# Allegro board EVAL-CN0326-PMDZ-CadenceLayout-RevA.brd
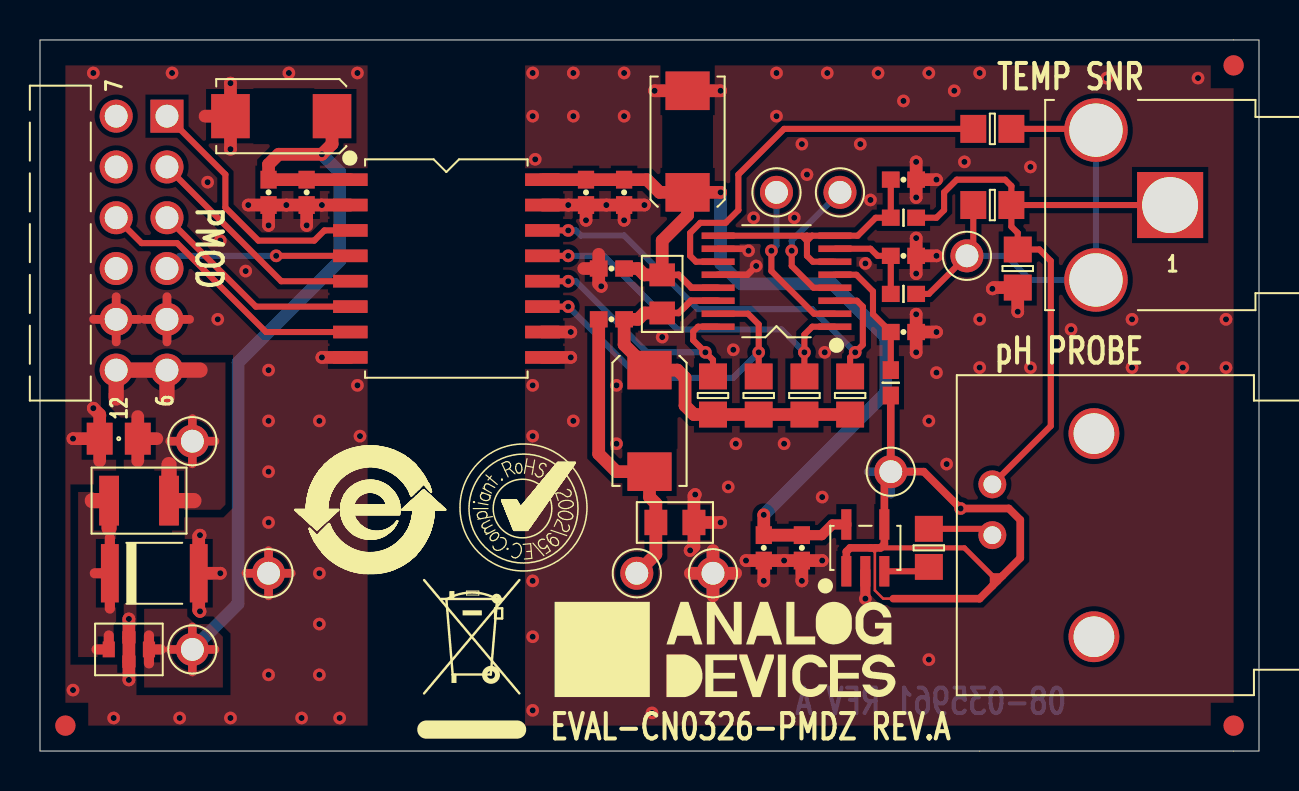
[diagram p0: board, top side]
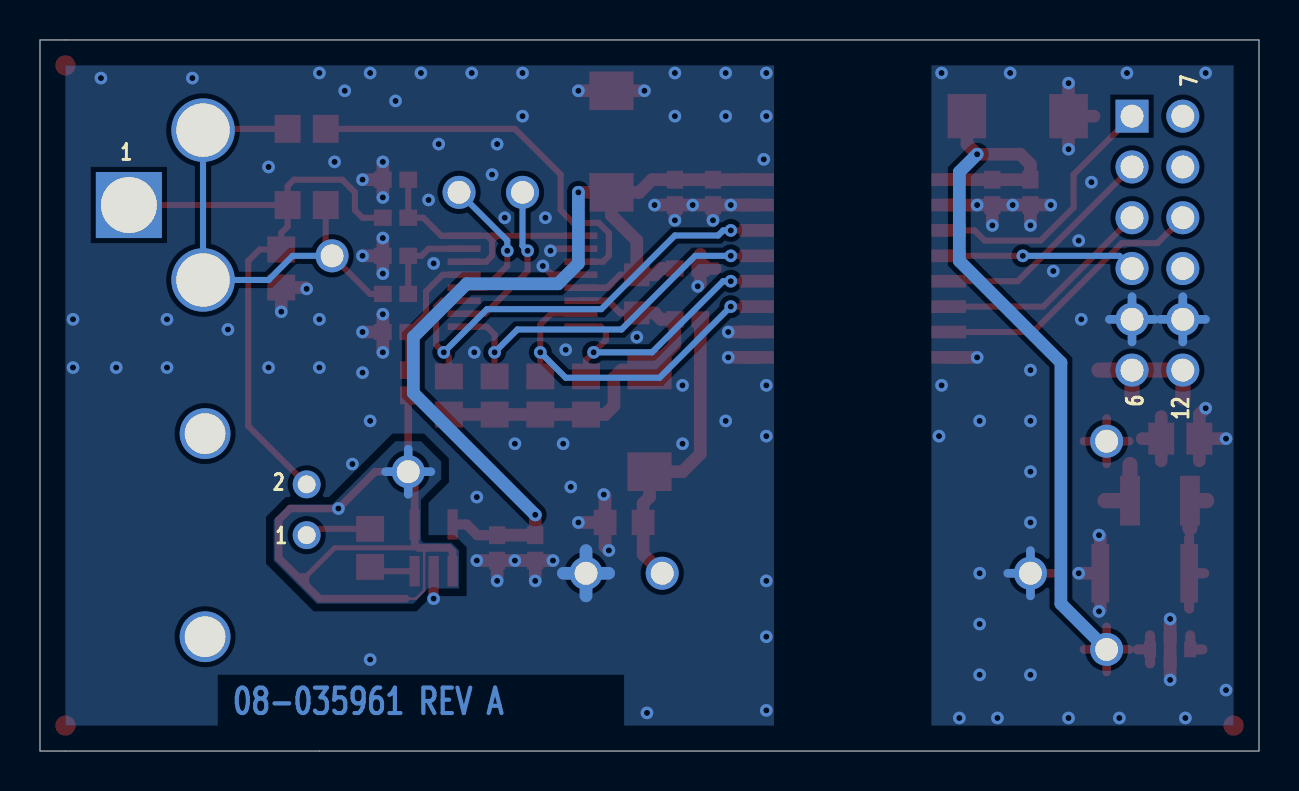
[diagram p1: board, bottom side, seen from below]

Outline 60.96 x 35.56 mm; copper layers: TOP, BOTTOM. Coordinates in mm from the lower left corner of the outline.
Outline path: 0,35.56 0,0 60.96,0 60.96,35.56 0,35.56

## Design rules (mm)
nets with their own width: min track width 0.508; nets AGND

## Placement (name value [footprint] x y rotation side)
C1  4.7UF  [C0805]  3.94 15.62 180 top
C2  100nF  [C0402]  36.2 10.16 90 top
C4  100nF  [C0402]  29.21 27.94 90 top
C5  10000pF  [C0402]  27.3 27.94 90 top
C6  10uF  [C2312]  12.06 31.75 180 top
C7  100nF  [C0402]  11.43 27.94 90 top
C8  10000pF  [C0402]  13.34 27.94 90 top
C9  10000pF  [C0402]  38.1 10.16 90 top
C10  1uF  [C0402]  43.18 20.95 180 top
C11  1uF  [C0402]  43.18 24.77 180 top
C12  1uF  [C0402]  43.18 28.57 180 top
C13  10uF  [C2312]  32.38 30.48 90 top
C14  100nF  [C0402]  28.58 24.13 0 top
C15  10uF  [C2312]  30.48 16.51 270 top
C16  100nF  [C0402]  28.58 21.59 0 top
CR1  DL4729A-TP  [DL41-2]  5.71 8.89 0 top
E1  330OHM  [L0805]  31.75 11.43 180 top
E2  330OHM  [L0805]  31.12 22.86 270 top
F1  0.35A  [F1210]  4.95 12.52 180 top
FR1  1uF  [C0805-4P]  4.44 5.08 0 top
J1  1-1634622-0  [CNAMP227161-1]  47.62 10.79 0 top
J2  TSW-106-25-F-D-RA  [CNHDRRA2X6H240]  6.35 31.75 270 top
NOREF  -  []  21.59 5.71 0 top
NOREF#2  -  [unnamed#2]  59.69 34.29 0 top
NOREF#3  -  []  -19.69 -47.12 0 top
NOREF#4  -  []  0 35.56 0 top
NOREF#5  -  []  60.96 0 90 top
NOREF#6  -  []  20.83 73.91 0 top
NOREF#7  -  []  0 0 0 top
NOREF#8  -  []  1.27 1.27 0 top
NOREF#9  -  []  0 0 0 top
NOREF#10  -  []  -136.53 -239.08 0 top
NOREF#11  -  [unnamed#2]  1.27 1.27 0 top
NOREF#12  -  []  60.96 0 90 top
NOREF#13  -  []  -136.53 -239.08 0 top
NOREF#14  -  []  0 0 0 top
NOREF#15  -  []  60.96 0 0 top
NOREF#16  -  []  60.96 35.56 180 top
NOREF#17  -  []  1.27 1.27 0 top
NOREF#18  -  []  16.51 12.06 0 top
NOREF#19  -  []  -136.53 -239.08 0 top
NOREF#20  -  []  24.13 12.06 0 top
NOREF#21  -  []  0 35.56 270 top
NOREF#22  -  []  34.29 5.08 0 top
NOREF#23  -  []  0 35.56 0 top
NOREF#24  -  [unnamed#2]  59.69 1.27 0 top
NOREF#25  -  []  -34.61 140.02 0 top
P1  PJRAN1X1U03X  [CNTHRAL768W394H522]  56.52 27.3 180 top
R1  5K  [R0805]  47.62 27.3 180 top
R2  5K  [R0805]  48.9 24.13 90 top
R3  0  [R0805]  47.62 31.11 0 top
R4  10K  [R0402]  42.55 18.41 90 top
R5  10K  [R0402]  43.18 22.86 180 top
R6  10K  [R0402]  43.18 26.67 180 top
R7  100K  [R0805]  40.51 17.78 270 top
R8  100K  [R0805]  38.23 17.78 270 top
R9  100K  [R0805]  33.66 17.78 90 top
R10  1MEG  [R0805]  44.45 10.16 270 top
R11  100K  [R0805]  35.94 17.78 90 top
TP1  TESTPAD  [TPC65D45]  7.62 15.49 180 top
TP2  TESTPAD  [TPC65D45]  42.55 13.97 0 top
TP3  TESTPAD  [TPC65D45]  46.36 24.77 0 top
TP4  TESTPAD  [TPC65D45]  7.62 5.08 180 top
TP5  TESTPAD  [TPC65D45]  33.66 8.89 0 top
TP6  TESTPAD  [TPC65D45]  29.84 8.89 0 top
TP7  TESTPAD  [TPC65D45]  36.83 27.94 180 top
TP8  TESTPAD  [TPC65D45]  40.01 27.94 180 top
TP19  TESTPAD  [TPC65D45]  11.43 8.89 0 top
U1  AD8603AUJZ  [TSOT-5]  41.27 10.16 0 top
U2  AD7793BRUZ  [TSSOP16]  36.83 23.5 90 top
U4  ADUM5401ARWZ  [SO16WB]  20.32 24.13 270 top

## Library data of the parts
C1 = CAP: Tolerance: 10; User Part Number: UPN; alternate symbols: (C0402H22_ALT,C0201-2,C0402_A); part number: CAP_SM-4.7UF,25V,10,E006908,C0805; tolerance: 10
C2 C4 C7 C14 C16 = CAP: Tolerance: 15; User Part Number: UPN; alternate symbols: (C0402H22_ALT,C0201-2,C0402_A); part number: CAP_SM-100NF,10V,15,E007265,C0402; tolerance: 15
C5 C8 C9 = CAP: Tolerance: 10; User Part Number: UPN; alternate symbols: (C0402H22_ALT,C0201-2,C0402_A); part number: CAP_SM-10000PF,25V,10,E013688,C0402; tolerance: 10
C6 C13 C15 = CAPP: Tolerance: 20; User Part Number: UPN; part number: CAPP_SM-10UF,35V,20,E013369,C2312; tolerance: 20
C10-C12 = CAP: Tolerance: 10; User Part Number: UPN; alternate symbols: (C0402H22_ALT,C0201-2,C0402_A); part number: CAP_SM-1UF,10V,10,E011429,C0402; tolerance: 10
CR1 = DIOZNR: Tolerance: 5; User Part Number: UPN; part number: DIOZNR_SM-DL4729A-TP,3.6V,5,E013494,DL41-2; tolerance: 5
E1 E2 = FERRITE: Tolerance: 25; User Part Number: UPN; part number: FERRITE_SM-330OHM,25,E018120,L0805; tolerance: 25
F1 = FSFUSE: User Part Number: UPN; part number: FSFUSE_SM-0.35A,6V,E016918,F1210
FR1 = CAP4P_V3: Tolerance: 20; User Part Number: UPN; part number: CAP4P_V3_SM-1UF,16V,20,E014204,C0805-4P; tolerance: 20
J1 = CNBNC2P: User Part Number: UPN; part number: CNBNC2P_TH-1-1634622-0,E008038,CNAMP227161-1
J2 = CN12P_V3: User Part Number: UPN; part number: CN12P_V3_TH-TSW-106-25-F-D-RA,E018495,CNHDRRA2X6H240
P1 = CN3P_V3: User Part Number: UPN; part number: CN3P_V3_TH-PJRAN1X1U03X,E013427,CNTHRAL768W394H522
R1 R2 = RES: Tolerance: 0.1; User Part Number: UPN; alternate symbols: (RRAD984L1500W75H520LD32;TO220H590_ALT;R0402_A); part number: RES_SM-5K,1/5W,0.1,E014315,R0805; tolerance: 0.1
R3 = RES: Tolerance: 1; User Part Number: UPN; alternate symbols: (RRAD984L1500W75H520LD32;TO220H590_ALT;R0402_A); part number: RES_SM-0,1/10W,1,E004152,R0805; tolerance: 1
R4-R6 = RES: Tolerance: 0.1; User Part Number: UPN; alternate symbols: (RRAD984L1500W75H520LD32;TO220H590_ALT;R0402_A); part number: RES_SM-10K,1/16W,0.1,E012474,R0402; tolerance: 0.1
R7-R9 R11 = RES: Tolerance: 0.1; User Part Number: UPN; alternate symbols: (RRAD984L1500W75H520LD32;TO220H590_ALT;R0402_A); part number: RES_SM-100K,1/10W,0.1,E003805,R0805; tolerance: 0.1
R10 = RES: Tolerance: 1; User Part Number: UPN; alternate symbols: (RRAD984L1500W75H520LD32;TO220H590_ALT;R0402_A); part number: RES_SM-1MEG,1/8W,1,E018283,R0805; tolerance: 1
TP1-TP8 TP19 = NCTESTPAD: User Part Number: UPN; part number: NCTESTPAD_TH-TESTPAD,E013404,TPC65D45
U1 = AD8603: User Part Number: UPN; part number: AD8603_SM-AD8603AUJZ,E007335,TSOT-5,AD8603
U2 = AD779X_V4: User Part Number: UPN; part number: AD779X_V4_SM-AD7793BRUZ,E018367,TSSOP16,N/A
U4 = ADUM5401: User Part Number: UPN; part number: ADUM5401_SM-ADUM5401ARWZ,E013987,SO16WB,N/A

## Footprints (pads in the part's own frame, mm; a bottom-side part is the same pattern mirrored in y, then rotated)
C0402
  rect 0.889x0.813 smd: 1(-0.635,0) 2(0.635,0)
C0805
  rect 1.295x1.6 smd: 1(-0.953,0) 2(0.953,0)
C0805-4P
  rect 0.61x0.787 smd: 1(-1.005,0) 3(1.005,0)
  rect 0.66x0.61 smd: G1(0,-0.605) G2(0,0.605)
C2312
  rect 1.93x2.21 smd: N(2.54,0) P(-2.54,0)
CNAMP227161-1
  round 2.54 hole 2.032: (5.08,5.08) (5.08,-5.08)
  round 1.397 hole 0.889: 1(0,0) 2(0,2.54)
CNHDRRA2X6H240
  rect 1.651x1.651 hole 1.143: 1(0,0)
  round 1.651 hole 1.143: 2(2.54,0) 3(5.08,0) 4(7.62,0) 5(10.16,0) 6(12.7,0) 7(0,-2.54) 8(2.54,-2.54) 9(5.08,-2.54) 10(7.62,-2.54) 11(10.16,-2.54) 12(12.7,-2.54)
CNTHRAL768W394H522
  rect 3.302x3.302 hole 2.794: 1(0,0)
  round 3.175 hole 2.667: 2(3.708,3.747) 3(3.708,-3.747)
DL41-2
  rect 0.889x2.921 smd: A(2.223,0) C(-2.223,0)
F1210
  rect 0.991x2.489 smd: 1(-1.499,0) 2(1.499,0)
L0805
  rect 1.143x1.27 smd: 1(-0.953,0) 2(0.953,0)
R0402
  rect 0.889x0.813 smd: 1(-0.635,0) 2(0.635,0)
R0805
  rect 1.295x1.397 smd: 1(-0.953,0) 2(0.953,0)
SO16WB
  rect 0.635x1.727 smd: 1(-4.445,-4.801) 2(-3.175,-4.801) 3(-1.905,-4.801) 4(-0.635,-4.801) 5(0.635,-4.801) 6(1.905,-4.801) 7(3.175,-4.801) 8(4.445,-4.801) 9(4.445,4.801) 10(3.175,4.801) 11(1.905,4.801) 12(0.635,4.801) 13(-0.635,4.801) 14(-1.905,4.801) 15(-3.175,4.801) 16(-4.445,4.801)
TPC65D45
  round 1.651 hole 1.143: 1(0,0)
TSOT-5
  rect 0.508x1.524 smd: 1(-0.95,-1.17) 2(0,-1.17) 3(0.95,-1.17) 4(0.95,1.17) 5(-0.95,1.17)
TSSOP16
  rect 0.33x1.651 smd: 1(-2.275,-2.92) 2(-1.625,-2.92) 3(-0.975,-2.92) 4(-0.325,-2.92) 5(0.325,-2.92) 6(0.975,-2.92) 7(1.625,-2.92) 8(2.275,-2.92) 9(2.275,2.92) 10(1.625,2.92) 11(0.975,2.92) 12(0.325,2.92) 13(-0.325,2.92) 14(-0.975,2.92) 15(-1.625,2.92) 16(-2.275,2.92)
unnamed#2
  round 1.016 smd: (0,0)

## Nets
AGND: C2.1(N1) C4.1(N1) C5.1(N1) C9.1(N1) C10.1(N1) C11.1(N1) C12.1(N1) C13.N(N2) C14.1(N1) E1.1(N1) R2.1(N1) TP5.1(N1) U1.2(VN) U2.10(REFIN-_AIN3-) U2.12(GND) U4.9(GNDISO1) U4.10(VSEL) U4.15(GNDISO2)
AGND_A: C15.N(N2) C16.1(N1) E1.2(N2) TP6.1(N1)
AVDD_ISO: C2.2(N2) C4.2(N2) C5.2(N2) C9.2(N2) C13.P(N1) C14.2(N2) E2.1(N1) U1.5(VP) U2.13(AVDD) U4.16(VISO)
DGND: C1.2(N2) C6.N(N2) C7.1(N1) C8.1(N1) CR1.A(P) FR1.G1(GND1) FR1.G2(GND2) J2.5(GND1) J2.11(GND2) TP19.1(N1) U4.2(GND1_1) U4.8(GND1_2)
DVDD_ISO: C15.P(N1) C16.2(N2) E2.2(N2) R7.2(N2) R8.2(N2) R9.1(N1) R11.1(N1) U2.14(DVDD)
VCC_A: C6.P(N1) C7.2(N2) C8.2(N2) FR1.3(OUT) TP4.1(N1) U4.1(VDD1)
CS_N: J2.1(P1) U4.3(VIA)
CS_N_ISO: R7.1(N1) U2.3(CS_N) U4.14(VOA)
DIN: J2.2(P2) U4.5(VIC)
DIN_ISO: R9.2(N2) U2.16(DIN) U4.12(VOC)
DOUT: J2.3(P3) U4.6(VOD)
DOUT_ISO: R11.2(N2) U2.15(DOUT_RDY_N) U4.11(VID)
RCOUT: J2.9(P9) U4.7(RCOUT)
SCLK: J2.4(P4) U4.4(VIB)
SCLK_ISO: R8.1(N1) U2.1(SCLK) U4.13(VOB)
UNNAMED_1_AD779XV4_I139_AIN1: C12.2(N2) R6.2(N2) U2.6(AIN1-) U2.8(AIN2-) U2.9(REFIN+_AIN3+)
UNNAMED_1_AD779XV4_I139_AIN1_1: C10.2(N2) R4.2(N2) U2.5(AIN1+)
UNNAMED_1_AD779XV4_I139_AIN2: C11.2(N2) R5.2(N2) U2.7(AIN2+)
UNNAMED_1_AD779XV4_I139_CLK: TP7.1(N1) U2.2(CLK)
UNNAMED_1_AD779XV4_I139_IOUT1: TP8.1(N1) U2.4(IOUT1)
UNNAMED_1_AD779XV4_I139_IOUT2: R3.1(N1) U2.11(IOUT2)
UNNAMED_1_AD8603_I1_INN: R4.1(N1) TP2.1(N1) U1.1(OUT) U1.4(IN_N)
UNNAMED_1_AD8603_I1_INP: R10.2(N2) U1.3(IN_P)
UNNAMED_1_CAP4PV3_I8_IN: CR1.C(N) F1.2(N2) FR1.1(IN)
UNNAMED_1_CAP_I5_N1: C1.1(N1) F1.1(N1) J2.6(VCC1) J2.12(VCC2) TP1.1(N1)
UNNAMED_1_CN3PV3_I233_N1: J1.2(SHIELD) P1.1(N1) R1.1(N1) R2.2(N2) R6.1(N1)
UNNAMED_1_CN3PV3_I233_N2: P1.2(N2) P1.3(N3) R1.2(N2) R3.2(N2) R5.1(N1) TP3.1(N1)
UNNAMED_1_CNBNC2P_I158_CNTR: J1.1(CNTR) R10.1(N1)

Pads without a net: J2 7 8 10

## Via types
v1: diameter 0.635, hole 0.305, TOP to BOTTOM, 142 vias

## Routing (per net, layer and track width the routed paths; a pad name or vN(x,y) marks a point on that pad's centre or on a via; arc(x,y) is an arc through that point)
AGND: length 50.3
  TOP w0.33: v1(35.81,24.26) 35.38,23.82 U2.12 ; v1(35.43,25.02) 35.33,25.12 U2.10
  TOP w0.508: U1.2 v1(41.27,7.62)
  TOP w0.635: C4.1 v1(29.21,26.54) ; C4.1 v1(30.23,27.3) ; C4.1 v1(28.32,27.3) C5.1 ; C2.1 v1(36.2,8.51) ; C2.1 v1(35.31,9.53) ; C2.1 v1(37.21,9.53) C9.1 ; C12.1 v1(43.82,29.46) ; C12.1 v1(44.83,28.57) ; C12.1 v1(43.82,27.69) ; C10.1 v1(44.83,20.95) ; C10.1 v1(43.82,19.94) ; C10.1 v1(43.82,21.84) ; U4.9 v1(26.54,19.68) ; C14.1 27.94,23.37 v1(28.07,23.24) ; C14.1 27.94,24.84 ; C14.1 27.19,24.13 ; v1(47.62,23.11) 47.69,23.18 R2.1 v1(48.9,21.97) ; v1(32.51,10.03) 32.7,10.22 E1.1 ; C11.1 v1(43.82,23.88) ; C11.1 v1(43.82,25.65) ; C11.1 v1(44.83,24.77) ; C5.1 v1(27.3,26.54) ; C5.1 v1(26.42,27.3) U4.15 ; 33.66,7.76 TP5.1 ; TP5.1 34.79,8.89 ; TP5.1 32.52,8.89 ; TP5.1 33.66,10.02 ; v1(30.73,33.02) C13.N v1(34.04,33.02) ; U4.10 v1(26.54,20.95) ; C9.1 v1(39.12,9.53) ; C9.1 v1(38.1,8.51) ; E1.1 32.7,12.76 v1(32.77,12.83) ; E1.1 v1(34.04,11.43)
  BOTTOM w0.635: 32.52,8.89 TP5.1 ; TP5.1 34.79,8.89 ; TP5.1 33.66,10.02 ; TP5.1 33.66,7.76
  vias: v1(24.64,33.91) v1(24.64,31.75) v1(24.64,18.29) v1(24.64,15.75) v1(24.64,8.51) v1(24.64,5.71) v1(24.64,2.03) v1(24.77,29.59) v1(26.67,33.91) v1(26.67,31.75) v1(26.67,16.51) v1(28.83,18.29) v1(28.83,15.37) v1(29.21,33.91) v1(29.21,31.75) v1(30.61,1.91) v1(31.12,20.7) v1(34.42,13.21) v1(34.67,20.07) v1(34.8,15.37) v1(35.69,26.67) v1(36.83,33.91) v1(36.83,31.75) v1(37.21,15.37) v1(37.72,26.67) v1(38.1,30.35) v1(38.35,28.83) v1(39.12,12.7) v1(39.24,19.94) v1(39.37,33.91) v1(41.02,30.35) v1(41.27,24.38) v1(41.53,27.56) v1(41.91,33.91) v1(43.18,32.51) v1(44.45,33.91) v1(44.45,16.51) v1(44.45,4.57) v1(44.83,18.92) v1(45.34,14.35) v1(45.72,33.02) v1(46.23,29.46) v1(46.99,33.91) v1(46.99,21.59) v1(46.99,19.18) v1(49.53,29.21) v1(49.53,19.18) v1(51.56,21.08) v1(53.34,33.66) v1(54.61,21.59) v1(54.61,19.18) v1(57.15,19.18) v1(57.91,33.66) v1(59.31,21.59) v1(59.31,19.18)
AGND_A: length 15.2
  TOP w0.635: TP6.1 30.8,9.84 E1.2 30.8,12.38 30.48,12.7 C15.N 28.83,13.97 27.94,14.86 C16.1
AVDD_ISO: length 49
  TOP w0.33: E2.1 31.94,23.81 32.58,23.17 U2.13
  TOP w0.508: C9.2 39.09,10.79 39.62,11.33 U1.5
  TOP w0.635: C13.P v1(34.04,27.94) ; C13.P 32.38,26.8 31.12,25.53 E2.1 30.23,23.81 29.91,24.13 C14.2 ; C13.P 30.99,27.94 30.35,28.57 U4.16 ; v1(36.2,11.81) C2.2 C9.2
  BOTTOM w0.635: v1(34.04,27.94) 34.04,24.38 35.05,23.37 39.62,23.37 42.29,20.7 42.29,17.91 v1(36.2,11.81)
DGND: length 51.2
  TOP w0.432: 10.3,8.89 TP19.1 ; TP19.1 12.56,8.89 ; TP19.1 11.43,10.02 ; TP19.1 11.43,7.76 ; 5.22,21.59 J2.5 ; J2.5 7.48,21.59 ; J2.5 6.35,22.72 ; J2.5 6.35,20.46 ; 3.81,20.46 J2.11 ; J2.11 3.81,22.72 ; J2.11 2.68,21.59 ; J2.11 4.94,21.59
  TOP w0.635: CR1.A 7.94,7.05 v1(8,6.98) ; CR1.A 7.94,10.73 v1(8,10.79) ; CR1.A v1(9.02,8.89) ; C8.1 v1(13.34,26.29) ; C8.1 v1(12.32,27.3) C7.1 ; C8.1 v1(14.1,27.3) U4.2 ; C6.N 8.25,31.75 ; C6.N v1(9.52,30.1) ; C6.N v1(9.52,33.4) ; v1(4.44,3.56) FR1.G1 FR1.G2 v1(4.44,6.6) ; C1.2 2.98,14.52 ; C1.2 v1(1.65,15.62) ; C1.2 2.98,16.83 v1(2.67,17.14) ; C7.1 v1(11.43,26.29) ; C7.1 v1(10.41,27.3) ; U4.8 v1(14.1,19.68)
  BOTTOM w0.432: J2.5 7.48,21.59 ; J2.5 5.22,21.59 ; J2.5 6.35,20.46 ; J2.5 6.35,22.72 ; 11.43,7.76 TP19.1 ; TP19.1 11.43,10.02 ; TP19.1 12.56,8.89 ; J2.11 4.94,21.59 ; J2.11 2.68,21.59 ; J2.11 3.81,22.72 ; J2.11 3.81,20.46
  vias: v1(1.65,3.05) v1(2.67,33.91) v1(3.68,1.65) v1(6.6,33.91) v1(6.98,1.65) v1(8.38,28.45) v1(8.89,21.59) v1(9.02,25.53) v1(9.52,1.65) v1(10.29,24) v1(11.43,19.05) v1(11.43,16.51) v1(11.43,13.97) v1(11.43,11.43) v1(11.43,3.81) v1(12.45,33.91) v1(13.08,1.65) v1(13.97,16.51) v1(13.97,8.89) v1(13.97,6.35) v1(13.97,3.81) v1(14.99,1.65) v1(15.88,33.91) v1(15.88,18.29) v1(16,15.75)
DVDD_ISO: length 19.9
  TOP w0.33: U2.14 32.55,22.52 31.94,21.91 E2.2
  TOP w0.635: E2.2 30.23,21.91 29.91,21.59 C16.2 29.21,20.32 C15.P 31.88,19.05 32.26,18.67 32.26,17.27 32.7,16.83 R9.1 R11.1 R8.2 R7.2
VCC_A: length 44.6
  TOP w0.432: TP4.1 7.62,6.21 ; TP4.1 6.49,5.08 ; TP4.1 7.62,3.95 ; TP4.1 8.75,5.08
  TOP w0.508: FR1.3 5.45,4.38 ; FR1.3 5.45,5.78 ; FR1.3 6.06,5.08
  TOP w0.635: 14.61,31.75 14.61,30.35 v1(14.1,29.84) 11.94,29.84 11.43,29.34 11.43,28.57 U4.1
  BOTTOM w0.635: TP4.1 9.91,7.37 9.91,19.43 14.99,24.51 14.99,28.96 v1(14.1,29.84)
CS_N: length 12.9
  TOP w0.305: J2.1 9.27,28.83 9.27,27.18 10.92,25.53 13.72,25.53 14.22,26.04 U4.3
CS_N_ISO: length 23.4
  TOP w0.305: U4.14 v1(26.42,26.04) ; R7.1 40.51,19.68 v1(40.77,19.94) 41.15,20.32 41.15,22.22 40.85,22.52 U2.3
  BOTTOM w0.305: v1(26.42,26.04) 26.8,26.04 27.05,25.78 29.21,25.78 32.89,22.1 38.61,22.1 v1(40.77,19.94)
DIN: length 11.5
  TOP w0.305: J2.2 12.06,23.5 U4.5
DIN_ISO: length 13.6
  TOP w0.305: U4.12 v1(26.42,23.5) ; R9.2 33.66,19.56 v1(33.27,19.94) 32.66,20.55 32.66,20.98 32.9,21.22 U2.16
  BOTTOM w0.305: v1(33.27,19.94) 30.35,19.94 26.8,23.5 v1(26.42,23.5)
DOUT: length 11
  TOP w0.305: J2.3 10.79,22.22 U4.6
DOUT_ISO: length 17.7
  TOP w0.305: U2.15 35.41,21.87 35.94,21.34 v1(35.94,19.94) R11.2 ; U4.11 v1(26.42,22.22)
  BOTTOM w0.305: v1(35.94,19.94) 34.67,18.67 29.97,18.67 v1(26.42,22.22)
RCOUT: length 14.1
  TOP w0.305: U4.7 11.3,20.95 6.86,25.4 5.08,25.4 J2.9
SCLK: length 9.4
  TOP w0.305: U4.4 v1(11.81,24.77)
  BOTTOM w0.305: J2.4 6.98,24.77 v1(11.81,24.77)
SCLK_ISO: length 18.9
  TOP w0.305: R8.1 v1(38.23,19.94) 38.23,20.83 38.62,21.22 U2.1 ; U4.13 v1(26.42,24.77)
  BOTTOM w0.305: v1(38.23,19.94) 37.08,21.08 31.88,21.08 28.19,24.77 v1(26.42,24.77)
UNNAMED_1_AD779XV4_I139_AIN1: length 14.1
  TOP w0.305: 38.35,25.53 38.36,25.53 38.61,25.77 ; 38.35,25.53 38.35,25.77 ; 38.35,25.53 38.34,25.53 38.1,25.77 ; 38.35,25.53 38.35,24.77 38.65,24.47 U2.6 ; 38.35,25.77 38.1,25.77 ; 38.35,25.77 38.61,25.77 ; 38.1,25.77 U2.9 ; 38.61,25.77 U2.8 40.89,25.77 41.79,26.67 R6.2 C12.2
UNNAMED_1_AD779XV4_I139_AIN1_1: length 6.6
  TOP w0.305: U2.5 40.82,23.82 41.66,22.99 41.66,21.84 C10.2 R4.2
UNNAMED_1_AD779XV4_I139_AIN2: length 4.8
  TOP w0.305: R5.2 C11.2 41.88,24.77 41.53,25.12 U2.7
UNNAMED_1_AD779XV4_I139_CLK: length 8.1
  TOP w0.305: U2.2 38.71,21.87 36.58,24 v1(36.58,25.02)
  BOTTOM w0.305: TP7.1 36.83,25.27 v1(36.58,25.02)
UNNAMED_1_AD779XV4_I139_IOUT1: length 7.3
  TOP w0.305: v1(37.59,25.02) 37.59,24.26 38.68,23.17 U2.4
  BOTTOM w0.305: TP8.1 37.59,25.53 v1(37.59,25.02)
UNNAMED_1_AD779XV4_I139_IOUT2: length 20
  TOP w0.305: U2.11 32.81,24.47 32.51,24.77 32.51,25.91 33.02,26.42 34.29,26.42 34.92,27.05 34.92,28.83 37.21,31.11 R3.1
UNNAMED_1_AD8603_I1_INN: length 42.8
  TOP w0.127: 41.75,9.94 41.75,8.03 42.16,7.62 42.67,7.62 ; 41.75,9.94 41.53,10.16 ; 41.75,9.94 41.75,10.13 41.78,10.16
  TOP w0.254: 42.04,10.16 46.23,10.16 47.62,8.76 ; 47.62,8.76 47.62,8.26 ; 47.62,8.76 47.88,8.51 ; 47.62,8.76 48.13,8.76
  TOP w0.381: TP2.1 44.2,13.97 v1(46.04,12.13) 48.45,12.13 49.02,11.56 49.02,9.65 46.99,7.62 42.67,7.62 ; TP2.1 R4.1 ; TP2.1 42.22,13.65 U1.4 42.22,10.35 42.04,10.16 40.51,10.16 40.33,9.97 U1.1
  BOTTOM w0.432: TP2.1 43.68,13.97 ; TP2.1 42.55,15.1 ; TP2.1 41.41,13.97 ; TP2.1 42.55,12.84
UNNAMED_1_AD8603_I1_INP: length 2.3
  TOP w0.305: R10.2 44.23,8.99 U1.3
UNNAMED_1_CAP4PV3_I8_IN: length 7.8
  TOP w0.508: CR1.C 2.74,8.89 ; CR1.C 3.49,7.12 ; CR1.C 3.49,10.66 ; 2.83,5.08 FR1.1 3.44,5.78
  TOP w0.762: 3.45,11.15 F1.2 2.62,12.52
UNNAMED_1_CAP_I5_N1: length 17.7
  TOP w0.432: 7.62,14.36 TP1.1 ; TP1.1 7.62,16.62 ; TP1.1 6.49,15.49 ; TP1.1 8.75,15.49
  TOP w0.635: C1.1 4.89,14.52 ; C1.1 5.84,15.62 ; C1.1 4.89,16.73
  TOP w0.762: 7.7,12.52 F1.1 6.45,14.33 ; J2.6 J2.12 3.81,17.65 ; J2.6 6.35,17.65 ; J2.6 8,19.05
UNNAMED_1_CN3PV3_I233_N1: length 31.7
  TOP w0.305: R1.1 P1.1 ; R1.1 48.58,26.23 48.9,25.91 R2.2 49.97,25.08 50.55,24.51 50.55,16.26 47.62,13.33 ; R1.1 48.58,28.26 48.26,28.57 45.85,28.57 45.21,27.94 45.21,27.05 44.83,26.67 R6.1
UNNAMED_1_CN3PV3_I233_N2: length 24.7
  TOP w0.305: R3.2 52.74,31.11 P1.3 ; R5.1 44.45,22.86 TP3.1 46.67,25.08 R1.2
  BOTTOM w0.305: P1.3 P1.2 49.53,23.56 48.32,24.77 TP3.1
UNNAMED_1_CNBNC2P_I158_CNTR: length 3.3
  TOP w0.305: J1.1 47.31,11.11 R10.1

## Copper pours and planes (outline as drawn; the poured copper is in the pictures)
AGND on TOP: 31.75,1.27 24.26,1.27 24.26,19.18 26.16,19.18 26.16,29.08 24.26,29.08 24.26,34.29 58.55,34.29 58.55,33.15 59.69,33.15 59.69,2.41 58.55,2.41 58.55,1.27 52.07,1.27 ; 6 cut-outs
AGND on BOTTOM: 24.26,1.27 24.26,34.29 59.69,34.29 59.69,1.27 52.07,1.27 52.07,3.81 31.75,3.81 31.75,1.27 ; 1 cut-out
DGND on TOP: 2.41,1.27 2.41,2.41 1.27,2.41 1.27,34.29 16.38,34.29 16.38,29.08 14.48,29.08 14.48,24.19 14.4,24.19 14.4,24.36 12.21,24.36 12.15,24.3 12.07,24.25 12.01,24.18 12.04,24.09 12.23,23.9 14.4,23.9 14.4,24.07 14.48,24.07 14.48,21.65 14.4,21.65 14.4,21.82 11.26,21.82 11.17,21.76 11.19,21.64 11.47,21.36 14.4,21.36 14.4,21.53 14.48,21.53 14.48,19.18 16.38,19.18 16.38,1.27 ; 2 cut-outs
DGND on BOTTOM: 1.27,1.27 1.27,34.29 16.38,34.29 16.38,1.27
VCC_A on TOP: 5.21,3.17 5.21,7.11 7.37,7.11 7.37,6.73 7.75,6.35 8.51,6.35 9.14,5.71 9.14,3.17
UNNAMED_1_AD8603_I1_INN on BOTTOM: 40.01,8.13 41.53,8.13 42.29,7.37 47.12,7.37 49.28,9.53 49.28,11.56 48.51,12.32 46.36,12.32 43.18,15.49 41.91,15.49 40.89,14.48 40.89,13.59 41.91,12.57 41.91,10.54 41.78,10.41 40.39,10.41 40.01,10.03
UNNAMED_1_CAP4PV3_I8_IN on TOP: 1.9,4.7 1.9,12.95 2.92,12.95 2.92,12.83 3.56,12.83 3.56,12.06 3.81,11.81 3.81,6.48 3.68,6.35 3.68,4.7
UNNAMED_1_CAP_I5_N1 on TOP: 5.71,14.1 4.19,14.1 4.19,16.51 3.43,17.27 3.43,19.43 9.27,19.43 9.27,12.32 9.02,12.06 5.71,12.06

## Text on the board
BOTTOM: 08-035961 REV A
Ref Des/Silkscreen Top: EVAL-CN0326-PMDZ REV.A | pH PROBE | TEMP SNR | PMOD
DIMENSION: REF
PAGE_OUTLINE: N/A | 24JUL12 | 20MAR13 | AD8067/ADA4091 CUSTOMER | EVALUATION BOARD | 20-035961
User.5: ROHS COMPLIANCE NOTE: | 100 MICRO INCHES NICKEL/ | 3-5 MICRO INCHES GOLD | HOMOGENOUS MATERIALS IN THIS BOARD SHALL BE COMPLIANT | THE EU RoHS DIRECTIVE 2002/95/EC
User.8: 08-      -01 | LAYER1 PRIMARY SIDE
User.9: 08-      -02 | LAYER2 SECONDARY SIDE
User.11: 08-      -07 | LAYER2_AGND
User.12: 08-      -08 | LAYER3_DGND
User.14: SECONDARY SIDE PASTEMASK | 08-      -12
User.27: 20-035961
User.33: FIGURE | SIZE | 12.0 | 35.0 | 45.0 | 80.0 | 105.0 | 110.0 | DRILL CHART: TOP to BOTTOM | ALL UNITS ARE IN MILS | TOLERANCE | +3.0/-3.0 | PLATED | QTY | 142 | 2 | 21 | 1
